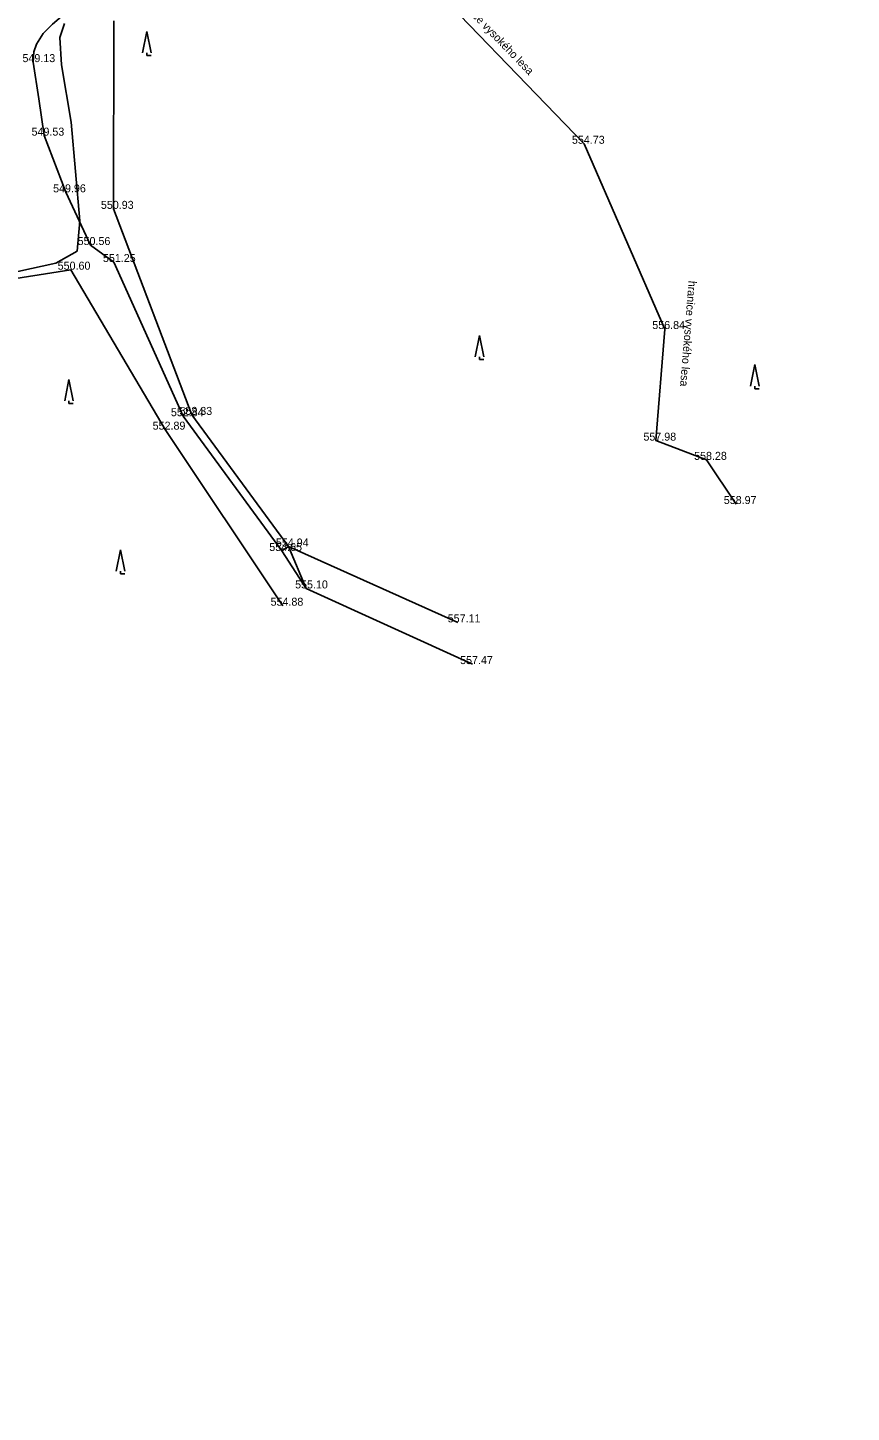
# Model space of a CAD drawing. Extents: x -669995 to -669686, y -1125551 to -1125263.
# Drawn here: x -669828.8 to -669751.7, y -1125550.5 to -1125420.8 of the extents above; entities that cross this region are included whole.
import ezdxf

# ---------------------------------------------------------------- set-up
doc = ezdxf.new("R2010")
doc.units = 0
for name, color, linetype in [('G_Bod_tecka', 7, 'Continuous'), ('G_Bod_vyska', 7, 'Continuous'), ('G_Breh_Teren', 7, 'Continuous'), ('G_Cesty_Schody', 7, 'Continuous'), ('G_Poznamky_odkaz', 7, 'Continuous'), ('G_Z_ELsilove_podz_kotovane', 7, 'Continuous'), ('G_Zelen-okraj', 7, 'Continuous'), ('G_Zelen-Znacky', 7, 'Continuous')]:
    doc.layers.add(name, color=color, linetype=linetype)

msp = doc.modelspace()

# ---------------------------------------------------------------- linework, layer by layer
at = {"layer": 'G_Bod_tecka'}
for p, q in [((-669828.32, -1125424), (-669828.32, -1125424)), ((-669827.31, -1125430.89), (-669827.31, -1125430.89)), ((-669776.68, -1125431.65), (-669776.68, -1125431.65)), ((-669825.28, -1125436.2), (-669825.28, -1125436.2)), ((-669820.79, -1125437.75), (-669820.79, -1125437.75)), ((-669822.96, -1125441.14), (-669822.96, -1125441.14)), ((-669824.81, -1125443.45), (-669824.81, -1125443.45)), ((-669820.77, -1125442.73), (-669820.77, -1125442.73)), ((-669769.13, -1125449.01), (-669769.13, -1125449.01)), ((-669814.26, -1125457.18), (-669814.26, -1125457.18)), ((-669813.46, -1125457.06), (-669813.46, -1125457.06)), ((-669815.96, -1125458.44), (-669815.96, -1125458.44)), ((-669769.97, -1125459.47), (-669769.97, -1125459.47)), ((-669765.23, -1125461.27), (-669765.23, -1125461.27)), ((-669762.44, -1125465.41), (-669762.44, -1125465.41)), ((-669804.41, -1125469.39), (-669804.41, -1125469.39)), ((-669805.02, -1125469.81), (-669805.02, -1125469.81)), ((-669802.74, -1125473.32), (-669802.74, -1125473.32)), ((-669804.92, -1125474.94), (-669804.92, -1125474.94)), ((-669788.52, -1125476.5), (-669788.52, -1125476.5)), ((-669787.16, -1125480.41), (-669787.16, -1125480.41))]:
    msp.add_line(p, q, dxfattribs=at)
at = {"layer": 'G_Breh_Teren'}
for p, q in [((-669820.77, -1125420.13), (-669820.79, -1125437.75)), ((-669820.79, -1125437.75), (-669813.46, -1125457.06))]:
    msp.add_line(p, q, dxfattribs=at)
for points in [[(-669813.46, -1125457.06), (-669804.41, -1125469.39)], [(-669805.02, -1125469.81), (-669804.41, -1125469.39)], [(-669804.41, -1125469.39), (-669802.74, -1125473.32)], [(-669804.41, -1125469.39), (-669788.52, -1125476.5)], [(-669787.16, -1125480.41), (-669802.74, -1125473.32)]]:
    msp.add_lwpolyline(points, dxfattribs=at)
at = {"layer": 'G_Cesty_Schody'}
msp.add_lwpolyline([(-669827.31, -1125430.89), (-669827.81, -1125427.44), (-669828.32, -1125424), (-669828.27, -1125423.02), (-669828.02, -1125422.32), (-669827.38, -1125421.32), (-669826.53, -1125420.43), (-669825.24, -1125419.34), (-669822.95, -1125417.69), (-669821.19, -1125416.63), (-669818.5, -1125415.21), (-669815.71, -1125413.85), (-669812.14, -1125411.91), (-669809.03, -1125410.3), (-669806.44, -1125409.64), (-669803.17, -1125408.56), (-669800.72, -1125407.98), (-669797.03, -1125407.45), (-669793.32, -1125407.28), (-669785.67, -1125407.31), (-669776.28, -1125408.27), (-669772.35, -1125408.22), (-669761.86, -1125407.64), (-669751.66, -1125407.06)], dxfattribs=at)
at = {"layer": 'G_Z_ELsilove_podz_kotovane'}
msp.add_lwpolyline([(-669863.58, -1125550.52), (-669862.33, -1125537.01), (-669860.37, -1125518.38), (-669858.01, -1125505.29), (-669856.03, -1125494.7), (-669852.89, -1125480.26), (-669850.98, -1125469.97), (-669849.59, -1125461.15), (-669849.27, -1125456.45), (-669847.81, -1125452.29), (-669846.73, -1125450.36), (-669839.33, -1125445.47), (-669833.36, -1125444.41), (-669826.21, -1125442.84), (-669824.2, -1125441.7), (-669823.97, -1125438.88), (-669824.78, -1125429.63), (-669825.67, -1125424.25), (-669825.82, -1125421.69), (-669825.4, -1125420.37)], dxfattribs=at)
at = {"layer": 'G_Zelen-okraj'}
for p, q in [((-669820.77, -1125442.73), (-669822.96, -1125441.14)), ((-669824.81, -1125443.45), (-669839.03, -1125445.7)), ((-669815.96, -1125458.44), (-669824.81, -1125443.45)), ((-669814.26, -1125457.18), (-669820.77, -1125442.73))]:
    msp.add_line(p, q, dxfattribs=at)
for points in [[(-669793.71, -1125414.01), (-669776.68, -1125431.65), (-669769.13, -1125449.01), (-669769.97, -1125459.47), (-669765.23, -1125461.27), (-669762.44, -1125465.41)], [(-669822.96, -1125441.14), (-669825.28, -1125436.2), (-669827.31, -1125430.89)], [(-669805.02, -1125469.81), (-669814.26, -1125457.18)], [(-669804.92, -1125474.94), (-669815.96, -1125458.44)], [(-669802.74, -1125473.32), (-669805.02, -1125469.81)]]:
    msp.add_lwpolyline(points, dxfattribs=at)
at = {"layer": 'G_Zelen-Znacky'}
for p, q in [((-669818.07, -1125423.14), (-669817.67, -1125421.14)), ((-669817.67, -1125421.14), (-669817.27, -1125423.14)), ((-669817.67, -1125423.14), (-669817.67, -1125423.39)), ((-669817.67, -1125423.39), (-669817.27, -1125423.39))]:
    msp.add_line(p, q, dxfattribs=at)
for points in [[(-669786.9, -1125451.62), (-669786.5, -1125449.62)], [(-669786.5, -1125449.62), (-669786.1, -1125451.62)], [(-669786.5, -1125451.62), (-669786.5, -1125451.87)], [(-669786.5, -1125451.87), (-669786.1, -1125451.87)], [(-669761.1, -1125454.35), (-669760.7, -1125452.35)], [(-669760.7, -1125452.35), (-669760.3, -1125454.35)], [(-669825.37, -1125455.74), (-669824.97, -1125453.74)], [(-669824.97, -1125453.74), (-669824.57, -1125455.74)], [(-669760.7, -1125454.35), (-669760.7, -1125454.6)], [(-669760.7, -1125454.6), (-669760.3, -1125454.6)], [(-669824.97, -1125455.74), (-669824.97, -1125455.99)], [(-669824.97, -1125455.99), (-669824.57, -1125455.99)], [(-669820.54, -1125471.69), (-669820.14, -1125469.69)], [(-669820.14, -1125469.69), (-669819.74, -1125471.69)], [(-669820.14, -1125471.69), (-669820.14, -1125471.94)], [(-669820.14, -1125471.94), (-669819.74, -1125471.94)]]:
    msp.add_lwpolyline(points, dxfattribs=at)

# ---------------------------------------------------------------- texts
at = {"layer": 'G_Bod_vyska'}
for s, p in [('549.13', (-669829.33, -1125424)), ('549.53', (-669828.48, -1125430.89)), ('554.73', (-669777.84, -1125431.65)), ('549.96', (-669826.46, -1125436.2)), ('550.93', (-669821.98, -1125437.75)), ('550.56', (-669824.16, -1125441.14)), ('551.25', (-669821.79, -1125442.73)), ('550.60', (-669826.03, -1125443.45)), ('556.84', (-669770.31, -1125449.01)), ('552.84', (-669815.42, -1125457.18)), ('553.33', (-669814.62, -1125457.06)), ('552.89', (-669817.13, -1125458.44)), ('557.98', (-669771.14, -1125459.47)), ('558.28', (-669766.39, -1125461.27)), ('558.97', (-669763.61, -1125465.41)), ('554.65', (-669806.2, -1125469.81)), ('554.94', (-669805.58, -1125469.39)), ('555.10', (-669803.78, -1125473.32)), ('554.88', (-669806.08, -1125474.94)), ('557.11', (-669789.48, -1125476.5)), ('557.47', (-669788.32, -1125480.41))]:
    msp.add_text(s, height=0.75, dxfattribs=at).set_placement(p)
at = {"layer": 'G_Poznamky_odkaz'}
for rotation, p in [(313.992, (-669788.77, -1125418.12)), (265.4087, (-669766.91, -1125444.47))]:
    msp.add_text('hranice vysokého lesa', height=0.75, rotation=rotation, dxfattribs=at).set_placement(p)

doc.saveas('drawing.dxf')
